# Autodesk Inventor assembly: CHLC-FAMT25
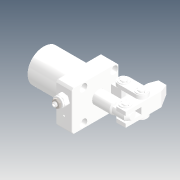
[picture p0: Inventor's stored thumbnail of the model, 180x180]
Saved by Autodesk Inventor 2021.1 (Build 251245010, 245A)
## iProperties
Created: 2019-04
Part Number: CHLC-FAMT25
Description: STEP AP214
Document SubType Name: Assembly
Designer: user
Title: CHLC-FAMT25.STEP
Revision Number: ÈÎºÎ
Sending System: SolidWorks 2016
Preprocessor: SwSTEP 2.0
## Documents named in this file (11)
- D:\Vault_2016\Projekty\Clamptek\Hydraulic\CHLC\CHLC-25\Inventor\CHLC-FAMT25\CHLC-FAMT25.iam
- D:\Vault_2016\Projekty\Clamptek\Hydraulic\CHLC\CHLC-25\Inventor\CHLC-FAMT25\CHLC-FAMT25_ASM.ipt
- D:\Vault_2016\Projekty\Clamptek\Hydraulic\CHLC\CHLC-25\Inventor\CHLC-FAMT25\CHLC-FAMT25BT.ipt
- D:\Vault_2016\Projekty\Clamptek\Hydraulic\CHLC\CHLC-25\Inventor\CHLC-FAMT25\CHLC-25ZC.ipt
- D:\Vault_2016\Projekty\Clamptek\Hydraulic\CHLC\CHLC-25\Inventor\CHLC-FAMT25\CHLC-25LG.ipt
- D:\Vault_2016\Projekty\Clamptek\Hydraulic\CHLC\CHLC-25\Inventor\CHLC-FAMT25\CHLC-25HSG.ipt
- D:\Vault_2016\Projekty\Clamptek\Hydraulic\CHLC\CHLC-25\Inventor\CHLC-FAMT25\CHLC-25DX.ipt
- D:\Vault_2016\Projekty\Clamptek\Hydraulic\CHLC\CHLC-25\Inventor\CHLC-FAMT25\CHLC-25CX.ipt
- D:\Vault_2016\Projekty\Clamptek\Hydraulic\CHLC\CHLC-25\Inventor\CHLC-FAMT25\CHLC-25KKDC.ipt
- D:\Vault_2016\Projekty\Clamptek\Hydraulic\CHLC\CHLC-25\Inventor\CHLC-FAMT25\Ñ¹±Û.ipt
- D:\Vault_2016\Projekty\Clamptek\Hydraulic\CHLC\CHLC-25\Inventor\CHLC-FAMT25\CZL10µ÷ËÙ·§.ipt
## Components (17 placed, 17 different names)
1. CHLC-FAMT25_ASM_1
2. CHLC-FAMT25BT_2
3. CHLC-25ZC_3
4. CHLC-25LG_4
5. CHLC-25LG_5
6. CHLC-25HSG_6
7. CHLC-25DX_7
8. CHLC-25CX_8
9. CHLC-25CX_9
10. CHLC-25KKDC_10
11. CHLC-25KKDC_11
12. CHLC-25KKDC_12
13. CHLC-25KKDC_13
14. CHLC-25KKDC_14
15. CHLC-25KKDC_15
16. Ñ¹±Û_16
17. CZL10µ÷ËÙ·§_17
